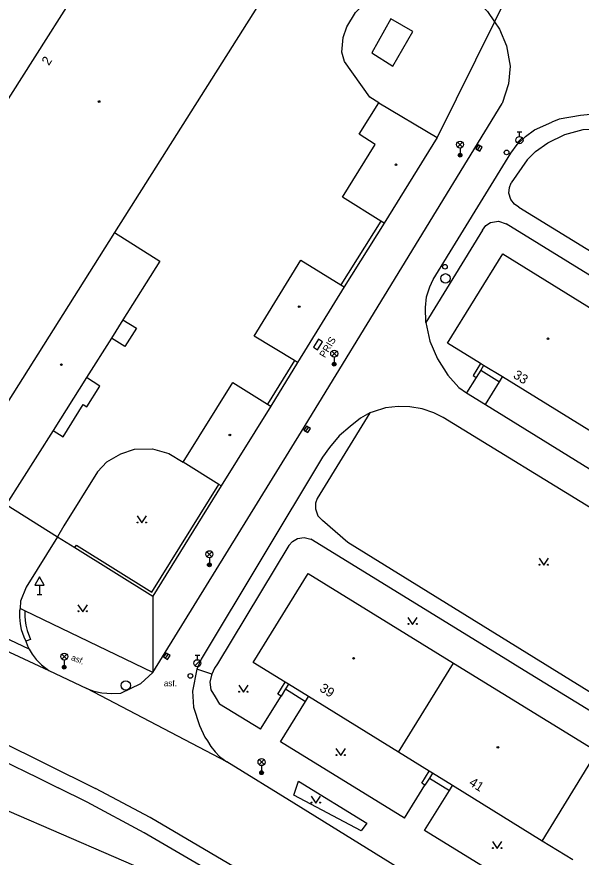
# Model space of a CAD drawing. Extents: x -598341 to -594502, y -1162301 to -1161406.
# Drawn here: x -594835.2 to -594775.2, y -1161589.1 to -1161499.6 of the extents above; entities that cross this region are included whole.
import ezdxf

# ---------------------------------------------------------------- set-up
doc = ezdxf.new("R2010")
doc.units = 0
for name, color, linetype in [('Vrstva 10', 7, 'Continuous'), ('Vrstva 11', 7, 'Continuous'), ('Vrstva 24', 7, 'Continuous'), ('Vrstva 27', 7, 'Continuous'), ('Vrstva 28', 7, 'Continuous'), ('Vrstva 33', 7, 'Continuous'), ('Vrstva 34', 7, 'Continuous'), ('Vrstva 36', 7, 'Continuous'), ('Vrstva 39', 7, 'Continuous'), ('Vrstva 40', 7, 'Continuous'), ('Vrstva 41', 7, 'Continuous'), ('Vrstva 46', 7, 'Continuous'), ('Vrstva 5', 7, 'Continuous'), ('Vrstva 7', 7, 'Continuous')]:
    doc.layers.add(name, color=color, linetype=linetype)

msp = doc.modelspace()

# ---------------------------------------------------------------- linework, layer by layer
at = {"layer": 'Vrstva 10'}
for p, q in [((-594777.5, -1161510.55), (-594778.28, -1161510.85)), ((-594775.22, -1161510.13), (-594777.5, -1161510.55)), ((-594772.93, -1161509.91), (-594775.22, -1161510.13)), ((-594791.68, -1161532.19), (-594791.26, -1161534.17)), ((-594791.26, -1161534.17), (-594790.44, -1161536.04)), ((-594790.44, -1161536.04), (-594789.33, -1161537.8)), ((-594789.33, -1161537.8), (-594788.16, -1161539.1)), ((-594788.16, -1161539.1), (-594787.34, -1161539.67)), ((-594787.34, -1161539.67), (-594785.33, -1161540.9)), ((-594785.33, -1161540.9), (-594772.03, -1161549.14)), ((-594797.27, -1161541.69), (-594797.64, -1161541.81)), ((-594795.98, -1161541.25), (-594797.27, -1161541.69)), ((-594794.61, -1161541.11), (-594795.98, -1161541.25)), ((-594793.4, -1161541.15), (-594794.61, -1161541.11)), ((-594792.09, -1161541.38), (-594793.4, -1161541.15)), ((-594790.82, -1161541.79), (-594792.09, -1161541.38)), ((-594789.84, -1161542.3), (-594790.82, -1161541.79)), ((-594768.35, -1161555.47), (-594789.84, -1161542.3)), ((-594831.79, -1161569.21), (-594827.75, -1161571.15))]:
    msp.add_line(p, q, dxfattribs=at)
for points in [[(-594800.34, -1161504.41), (-594800.62, -1161503.39), (-594800.48, -1161501.86), (-594800.1, -1161500.69), (-594799.15, -1161499.17), (-594798.28, -1161498.33), (-594796.95, -1161497.48), (-594796.01, -1161497), (-594793.91, -1161496.37), (-594791.34, -1161496.15), (-594790.25, -1161496.27), (-594788.22, -1161496.9), (-594786.62, -1161497.74), (-594785.86, -1161498.38), (-594785.12, -1161499.06), (-594784.39, -1161500.16)], [(-594784.39, -1161500.16), (-594783.86, -1161500.95), (-594783.09, -1161502.73), (-594782.71, -1161504.89), (-594782.88, -1161506.78), (-594783.57, -1161508.88)], [(-594796.69, -1161508.79), (-594797.64, -1161508.2), (-594800.34, -1161504.41)], [(-594820.71, -1161569.44), (-594804.92, -1161543.78), (-594783.57, -1161508.88)], [(-594782.64, -1161514.17), (-594781.95, -1161513.24), (-594781.08, -1161512.39), (-594780.12, -1161511.67), (-594778.28, -1161510.85)], [(-594791.68, -1161532.19), (-594791.72, -1161530.58), (-594791.62, -1161529.44), (-594791.26, -1161528.4), (-594790.9, -1161527.6), (-594782.64, -1161514.17)], [(-594797.64, -1161541.81), (-594798.64, -1161542.35), (-594799.74, -1161543.26), (-594800.89, -1161544.26), (-594801.92, -1161545.48), (-594802.66, -1161546.53), (-594815.59, -1161568), (-594816.06, -1161569.07)], [(-594826.63, -1161548.06), (-594825.61, -1161547), (-594824.14, -1161546.17), (-594822.68, -1161545.68), (-594820.76, -1161545.64), (-594819.01, -1161546.13), (-594817.5, -1161547.06)], [(-594826.63, -1161548.06), (-594830.18, -1161553.84), (-594830.88, -1161554.98)], [(-594830.88, -1161554.98), (-594834.21, -1161560.36), (-594834.81, -1161561.86), (-594834.84, -1161562.63)], [(-594872.63, -1161561.39), (-594861.47, -1161565.85), (-594849.95, -1161570.68), (-594837.2, -1161576.65), (-594826.82, -1161581.77)], [(-594834.84, -1161562.63), (-594834.91, -1161562.87), (-594834.92, -1161563.53), (-594834.84, -1161564.24), (-594834.72, -1161564.87), (-594834.44, -1161565.64), (-594834.25, -1161566.1)], [(-594834.25, -1161566.1), (-594834.05, -1161566.58), (-594833.88, -1161566.95)], [(-594833.88, -1161566.95), (-594833.56, -1161567.5), (-594833.15, -1161568.05), (-594832.57, -1161568.63), (-594831.79, -1161569.21)], [(-594827.75, -1161571.15), (-594827.01, -1161571.41), (-594826.14, -1161571.59), (-594825.1, -1161571.67), (-594824.12, -1161571.62), (-594822, -1161570.62), (-594820.71, -1161569.44)], [(-594816.06, -1161569.07), (-594816.51, -1161571.43)], [(-594816.51, -1161571.43), (-594816.39, -1161573.11), (-594815.76, -1161575.07), (-594815.18, -1161576.31), (-594814.92, -1161576.7), (-594814.56, -1161577.31), (-594814.11, -1161577.89), (-594813.62, -1161578.38), (-594812.86, -1161578.94)], [(-594667.97, -1161668.53), (-594669.66, -1161667.48), (-594695.85, -1161651.27), (-594736.44, -1161626.19), (-594748.94, -1161618.48), (-594759.37, -1161612.03), (-594780.07, -1161599.23), (-594788.49, -1161594.04), (-594805.73, -1161583.35), (-594812.86, -1161578.94)], [(-594753.01, -1161626.46), (-594785.35, -1161606.48), (-594808.52, -1161592.2), (-594811.42, -1161590.51), (-594821.01, -1161584.87), (-594826.82, -1161581.77)]]:
    msp.add_lwpolyline(points, dxfattribs=at)
at = {"layer": 'Vrstva 11'}
for p, q in [((-594781.36, -1161494.02), (-594784.39, -1161500.16)), ((-594784.39, -1161500.16), (-594790.47, -1161512.47)), ((-594780, -1161513.97), (-594780.91, -1161514.88)), ((-594780.91, -1161514.88), (-594782.6, -1161517.32)), ((-594781.79, -1161519.92), (-594767.3, -1161528.78)), ((-594796.47, -1161521.38), (-594800.71, -1161528.17)), ((-594796.13, -1161521.59), (-594800.37, -1161528.38)), ((-594762.67, -1161534.31), (-594783.13, -1161521.66)), ((-594785.65, -1161522.35), (-594791.68, -1161532.19)), ((-594805.67, -1161536.24), (-594808.52, -1161540.86)), ((-594805.33, -1161536.45), (-594808.18, -1161541.07)), ((-594785.84, -1161537.25), (-594786.32, -1161538.02)), ((-594785.53, -1161536.74), (-594785.84, -1161537.25)), ((-594785.84, -1161537.25), (-594783.84, -1161538.49)), ((-594786.32, -1161538.02), (-594787.34, -1161539.67)), ((-594783.84, -1161538.49), (-594783.52, -1161537.98)), ((-594785.33, -1161540.9), (-594783.84, -1161538.49)), ((-594797.64, -1161541.81), (-594803.24, -1161550.93)), ((-594813.46, -1161549.57), (-594820.73, -1161561.3)), ((-594836.32, -1161551.56), (-594830.88, -1161554.98)), ((-594830.88, -1161554.98), (-594829.01, -1161556.13)), ((-594783.47, -1161567.83), (-594803.9, -1161555.23)), ((-594829.01, -1161556.13), (-594820.73, -1161561.3)), ((-594806.25, -1161555.9), (-594813.86, -1161568.5)), ((-594820.73, -1161561.3), (-594820.71, -1161569.44)), ((-594833.88, -1161566.95), (-594844.6, -1161561.96)), ((-594813.86, -1161568.5), (-594814.15, -1161568.99)), ((-594781.69, -1161568.93), (-594783.47, -1161567.83)), ((-594814.44, -1161569.62), (-594816.06, -1161569.07)), ((-594814.15, -1161568.99), (-594814.44, -1161569.62)), ((-594751.86, -1161587.33), (-594781.69, -1161568.93)), ((-594814.49, -1161569.72), (-594814.66, -1161570.46)), ((-594814.66, -1161570.46), (-594814.56, -1161571.27)), ((-594814.44, -1161569.62), (-594814.49, -1161569.72)), ((-594812.86, -1161578.94), (-594827.75, -1161571.15)), ((-594814.56, -1161571.27), (-594814.1, -1161572.03)), ((-594806.62, -1161571.19), (-594807.09, -1161571.96)), ((-594806.3, -1161570.68), (-594806.62, -1161571.19)), ((-594806.62, -1161571.19), (-594804.49, -1161572.51)), ((-594814.1, -1161572.03), (-594813.65, -1161572.79)), ((-594809.28, -1161575.48), (-594807.09, -1161571.96)), ((-594804.49, -1161572.51), (-594804.18, -1161572)), ((-594809.28, -1161575.48), (-594813.65, -1161572.79)), ((-594807.15, -1161576.8), (-594804.49, -1161572.51)), ((-594793.94, -1161584.93), (-594807.15, -1161576.8)), ((-594790.99, -1161580.16), (-594791.3, -1161580.67)), ((-594791.3, -1161580.67), (-594791.78, -1161581.43)), ((-594791.3, -1161580.67), (-594789.18, -1161581.98)), ((-594793.94, -1161584.93), (-594791.78, -1161581.43)), ((-594791.81, -1161586.24), (-594789.18, -1161581.98)), ((-594789.18, -1161581.98), (-594788.86, -1161581.47)), ((-594778.65, -1161594.35), (-594791.81, -1161586.24))]:
    msp.add_line(p, q, dxfattribs=at)
for points in [[(-594795.42, -1161499.85), (-594797.41, -1161503.48), (-594795.19, -1161504.9), (-594793.05, -1161501.22), (-594795.42, -1161499.85)], [(-594780, -1161513.97), (-594778.7, -1161513.04), (-594776.88, -1161512.17), (-594774.96, -1161511.65), (-594773.18, -1161511.58), (-594771.62, -1161511.7)], [(-594781.79, -1161519.92), (-594782.25, -1161519.58), (-594782.63, -1161519.07), (-594782.86, -1161518.41), (-594782.79, -1161517.82), (-594782.6, -1161517.32)], [(-594785.65, -1161522.35), (-594785.3, -1161521.86), (-594784.8, -1161521.53), (-594783.96, -1161521.39), (-594783.13, -1161521.66)], [(-594823.91, -1161531.88), (-594822.48, -1161532.78), (-594823.71, -1161534.74), (-594825.14, -1161533.84)], [(-594785.87, -1161536.53), (-594786.66, -1161537.81), (-594786.32, -1161538.02)], [(-594831.34, -1161543.67), (-594830.28, -1161544.34), (-594828.12, -1161540.92), (-594827.75, -1161541.15), (-594826.36, -1161538.94), (-594827.79, -1161538.04)], [(-594829.01, -1161556.13), (-594828.85, -1161555.88), (-594820.83, -1161560.89), (-594813.72, -1161549.41)], [(-594803.24, -1161550.93), (-594803.42, -1161551.41), (-594803.42, -1161552), (-594803.17, -1161552.75), (-594802.68, -1161553.27)], [(-594753.34, -1161584.44), (-594799.98, -1161555.58), (-594802.68, -1161553.27)], [(-594806.25, -1161555.9), (-594805.88, -1161555.48), (-594805.32, -1161555.18), (-594804.64, -1161555.08), (-594803.9, -1161555.23)], [(-594847.56, -1161561.8), (-594846.03, -1161562.58), (-594831.79, -1161569.21)], [(-594873.3, -1161563.07), (-594862.11, -1161567.55), (-594851.19, -1161572.09), (-594850.78, -1161572.28), (-594843.93, -1161575.41), (-594837.87, -1161578.23), (-594836.8, -1161578.76), (-594833.01, -1161580.6), (-594830.81, -1161581.71)], [(-594834.36, -1161562.88), (-594834.84, -1161562.63)], [(-594834.36, -1161562.88), (-594834.36, -1161563.44), (-594834.32, -1161563.9), (-594834.23, -1161564.41), (-594834.09, -1161564.95), (-594833.74, -1161565.91), (-594834.25, -1161566.1)], [(-594820.71, -1161569.44), (-594834.36, -1161562.88)], [(-594807.09, -1161571.96), (-594807.43, -1161571.74), (-594806.64, -1161570.47)], [(-594791.78, -1161581.43), (-594792.12, -1161581.22), (-594791.33, -1161579.94)], [(-594797.97, -1161585.48), (-594798.57, -1161586.29), (-594805.72, -1161582.5), (-594805.22, -1161581.01), (-594797.97, -1161585.48)], [(-594812.28, -1161591.96), (-594821.65, -1161586.5), (-594827.72, -1161583.25), (-594830.81, -1161581.71)]]:
    msp.add_lwpolyline(points, dxfattribs=at)
at = {"layer": 'Vrstva 24'}
msp.add_lwpolyline([(-594803.21, -1161535.076), (-594802.67, -1161534.234), (-594803.09, -1161533.964), (-594803.63, -1161534.806)], close=True, dxfattribs=at)
at = {"layer": 'Vrstva 27'}
for p, q in [((-594786.15, -1161513.813), (-594785.89, -1161513.387)), ((-594804.434, -1161543.761), (-594804.166, -1161543.339)), ((-594819.379, -1161567.918), (-594819.101, -1161567.502))]:
    msp.add_line(p, q, dxfattribs=at)
for points in [[(-594785.937, -1161513.944), (-594785.676, -1161513.517), (-594786.103, -1161513.256), (-594786.364, -1161513.683)], [(-594804.223, -1161543.895), (-594803.955, -1161543.473), (-594804.377, -1161543.205), (-594804.645, -1161543.627)], [(-594819.171, -1161568.057), (-594818.893, -1161567.641), (-594819.309, -1161567.363), (-594819.587, -1161567.779)]]:
    msp.add_lwpolyline(points, close=True, dxfattribs=at)
for centre in [(-594789.59, -1161527.48), (-594823.6, -1161570.81)]:
    msp.add_circle(centre, 0.5, dxfattribs=at)
at = {"layer": 'Vrstva 28'}
for p, q in [((-594781.97, -1161511.895), (-594781.47, -1161511.895)), ((-594781.72, -1161512.395), (-594781.72, -1161511.895)), ((-594781.978, -1161513.042), (-594781.448, -1161512.512)), ((-594816.24, -1161567.575), (-594815.74, -1161567.575)), ((-594815.99, -1161568.075), (-594815.99, -1161567.575)), ((-594816.248, -1161568.722), (-594815.718, -1161568.192))]:
    msp.add_line(p, q, dxfattribs=at)
for centre, radius in [((-594781.72, -1161512.77), 0.375), ((-594783.09, -1161514.08), 0.25), ((-594789.65, -1161526.24), 0.25), ((-594815.99, -1161568.45), 0.375), ((-594816.73, -1161569.8), 0.25)]:
    msp.add_circle(centre, radius, dxfattribs=at)
at = {"layer": 'Vrstva 33'}
for p, q in [((-594788.305, -1161513.51), (-594787.775, -1161512.98)), ((-594788.305, -1161512.98), (-594787.775, -1161513.51)), ((-594788.04, -1161513.62), (-594788.04, -1161514.37)), ((-594801.695, -1161535.76), (-594801.165, -1161535.23)), ((-594801.695, -1161535.23), (-594801.165, -1161535.76)), ((-594801.43, -1161535.87), (-594801.43, -1161536.62)), ((-594814.975, -1161557.11), (-594814.445, -1161556.58)), ((-594814.975, -1161556.58), (-594814.445, -1161557.11)), ((-594814.71, -1161557.22), (-594814.71, -1161557.97)), ((-594830.415, -1161568.01), (-594829.885, -1161567.48)), ((-594830.415, -1161567.48), (-594829.885, -1161568.01)), ((-594830.15, -1161568.12), (-594830.15, -1161568.87)), ((-594809.425, -1161579.24), (-594808.895, -1161578.71)), ((-594809.425, -1161578.71), (-594808.895, -1161579.24)), ((-594809.16, -1161579.35), (-594809.16, -1161580.1))]:
    msp.add_line(p, q, dxfattribs=at)
for centre, radius in [((-594788.04, -1161513.245), 0.375), ((-594788.04, -1161514.37), 0.2), ((-594788.04, -1161514.37), 0.145), ((-594788.04, -1161514.37), 0.0876), ((-594801.43, -1161535.495), 0.375), ((-594801.43, -1161536.62), 0.2), ((-594801.43, -1161536.62), 0.145), ((-594801.43, -1161536.62), 0.0876), ((-594814.71, -1161556.845), 0.375), ((-594814.71, -1161557.97), 0.2), ((-594814.71, -1161557.97), 0.145), ((-594814.71, -1161557.97), 0.0876), ((-594830.15, -1161567.745), 0.375), ((-594830.15, -1161568.87), 0.2), ((-594830.15, -1161568.87), 0.145), ((-594830.15, -1161568.87), 0.0876), ((-594809.16, -1161578.975), 0.375), ((-594809.16, -1161580.1), 0.2), ((-594809.16, -1161580.1), 0.145), ((-594809.16, -1161580.1), 0.0876)]:
    msp.add_circle(centre, radius, dxfattribs=at)
at = {"layer": 'Vrstva 34'}
for p, q in [((-594832.79, -1161560.122), (-594832.79, -1161561.14)), ((-594833.04, -1161561.14), (-594832.54, -1161561.14))]:
    msp.add_line(p, q, dxfattribs=at)
msp.add_lwpolyline([(-594833.29, -1161560.122), (-594832.29, -1161560.122), (-594832.79, -1161559.256)], close=True, dxfattribs=at)
at = {"layer": 'Vrstva 36'}
for points in [[(-594822.39, -1161552.77), (-594821.89, -1161553.52), (-594821.39, -1161552.77)], [(-594779.64, -1161557.27), (-594779.14, -1161558.02), (-594778.64, -1161557.27)], [(-594828.69, -1161562.22), (-594828.19, -1161562.97), (-594827.69, -1161562.22)], [(-594793.59, -1161563.57), (-594793.09, -1161564.32), (-594792.59, -1161563.57)], [(-594811.59, -1161570.78), (-594811.09, -1161571.53), (-594810.59, -1161570.78)], [(-594801.24, -1161577.53), (-594800.74, -1161578.28), (-594800.24, -1161577.53)], [(-594803.89, -1161582.59), (-594803.39, -1161583.34), (-594802.89, -1161582.59)], [(-594784.59, -1161587.43), (-594784.09, -1161588.18), (-594783.59, -1161587.43)]]:
    msp.add_lwpolyline(points, dxfattribs=at)
for centre in [(-594822.34, -1161553.47), (-594821.441, -1161553.47), (-594779.59, -1161557.97), (-594778.691, -1161557.97), (-594828.64, -1161562.92), (-594827.741, -1161562.92), (-594793.54, -1161564.27), (-594792.641, -1161564.27), (-594811.54, -1161571.48), (-594810.641, -1161571.48), (-594801.19, -1161578.23), (-594800.291, -1161578.23), (-594803.84, -1161583.29), (-594802.941, -1161583.29), (-594784.54, -1161588.13), (-594783.641, -1161588.13)]:
    msp.add_circle(centre, 0.05, dxfattribs=at)
at = {"layer": 'Vrstva 39'}
for centre, radius in [((-594826.44, -1161508.66), 0.09), ((-594826.44, -1161508.66), 0.0398), ((-594794.86, -1161515.39), 0.09), ((-594794.86, -1161515.39), 0.0398), ((-594805.15, -1161530.5), 0.09), ((-594805.15, -1161530.5), 0.0398), ((-594778.69, -1161533.91), 0.09), ((-594778.69, -1161533.91), 0.0398), ((-594830.46, -1161536.67), 0.09), ((-594830.46, -1161536.67), 0.0398), ((-594812.53, -1161544.15), 0.09), ((-594812.53, -1161544.15), 0.0398), ((-594799.36, -1161567.93), 0.09), ((-594799.36, -1161567.93), 0.0398), ((-594784.02, -1161577.4), 0.09), ((-594784.02, -1161577.4), 0.0398)]:
    msp.add_circle(centre, radius, dxfattribs=at)
at = {"layer": 'Vrstva 5'}
for p, q in [((-594839.26, -1161513.37), (-594813.52, -1161472.72)), ((-594799.12, -1161481.9), (-594824.8, -1161522.6)), ((-594798.78, -1161512.15), (-594796.69, -1161508.79)), ((-594796.69, -1161508.79), (-594790.47, -1161512.47)), ((-594797.06, -1161513.22), (-594798.78, -1161512.15)), ((-594800.55, -1161518.85), (-594797.06, -1161513.22)), ((-594790.47, -1161512.47), (-594796.13, -1161521.59)), ((-594796.47, -1161521.38), (-594800.55, -1161518.85)), ((-594796.13, -1161521.59), (-594796.47, -1161521.38)), ((-594824.8, -1161522.6), (-594837.89, -1161543.36)), ((-594824.8, -1161522.6), (-594819.97, -1161525.65)), ((-594819.97, -1161525.65), (-594823.91, -1161531.88)), ((-594809.93, -1161533.62), (-594804.97, -1161525.55)), ((-594804.97, -1161525.55), (-594800.71, -1161528.17)), ((-594789.36, -1161534.37), (-594783.49, -1161524.88)), ((-594783.49, -1161524.88), (-594768.02, -1161534.45)), ((-594800.37, -1161528.38), (-594805.33, -1161536.45)), ((-594800.71, -1161528.17), (-594800.37, -1161528.38)), ((-594823.91, -1161531.88), (-594825.14, -1161533.84)), ((-594805.67, -1161536.24), (-594809.93, -1161533.62)), ((-594825.14, -1161533.84), (-594827.79, -1161538.04)), ((-594785.87, -1161536.53), (-594789.36, -1161534.37)), ((-594805.33, -1161536.45), (-594805.67, -1161536.24)), ((-594785.53, -1161536.74), (-594785.87, -1161536.53)), ((-594783.52, -1161537.98), (-594785.53, -1161536.74)), ((-594827.79, -1161538.04), (-594831.34, -1161543.67)), ((-594773.89, -1161543.94), (-594783.52, -1161537.98)), ((-594817.5, -1161547.06), (-594812.22, -1161538.56)), ((-594812.22, -1161538.56), (-594808.52, -1161540.86)), ((-594808.52, -1161540.86), (-594808.18, -1161541.07)), ((-594808.18, -1161541.07), (-594813.46, -1161549.57)), ((-594831.34, -1161543.67), (-594836.32, -1161551.56)), ((-594813.72, -1161549.41), (-594817.5, -1161547.06)), ((-594813.46, -1161549.57), (-594813.72, -1161549.41)), ((-594810.04, -1161568.37), (-594804.19, -1161558.91)), ((-594804.19, -1161558.91), (-594788.74, -1161568.43)), ((-594806.64, -1161570.47), (-594810.04, -1161568.37)), ((-594794.59, -1161577.93), (-594788.74, -1161568.43)), ((-594788.74, -1161568.43), (-594773.44, -1161577.86)), ((-594806.3, -1161570.68), (-594806.64, -1161570.47)), ((-594804.18, -1161572), (-594806.3, -1161570.68)), ((-594794.59, -1161577.93), (-594804.18, -1161572)), ((-594791.33, -1161579.94), (-594794.59, -1161577.93)), ((-594779.31, -1161587.38), (-594773.44, -1161577.86)), ((-594790.99, -1161580.16), (-594791.33, -1161579.94)), ((-594788.86, -1161581.47), (-594790.99, -1161580.16)), ((-594779.31, -1161587.38), (-594788.86, -1161581.47)), ((-594776.06, -1161589.39), (-594779.31, -1161587.38))]:
    msp.add_line(p, q, dxfattribs=at)
at = {"layer": 'Vrstva 7'}
msp.add_lwpolyline([(-594865.05, -1161572.22), (-594861.92, -1161572.7), (-594836.04, -1161584.2), (-594813.76, -1161593.84)], dxfattribs=at)

# ---------------------------------------------------------------- texts
at = {"layer": 'Vrstva 40'}
msp.add_text(' asf.', height=0.65, rotation=338.04338, dxfattribs=at).set_placement((-594829.7, -1161567.99))
msp.add_text('asf.', height=0.65, dxfattribs=at).set_placement((-594819.56, -1161570.9))
at = {"layer": 'Vrstva 41'}
msp.add_text('PRIS', height=0.75, rotation=58.90214, dxfattribs=at).set_placement((-594802.42, -1161536))
at = {"layer": 'Vrstva 46'}
for s, rotation, p in [('2', 57.66, (-594831.79, -1161504.89)), ('33', 327.9, (-594782.47, -1161538.01)), ('39', 327.64, (-594803.07, -1161571.35)), ('41', 327.98, (-594787.17, -1161581.38))]:
    msp.add_text(s, height=1, rotation=rotation, dxfattribs=at).set_placement(p)

doc.saveas('drawing.dxf')
